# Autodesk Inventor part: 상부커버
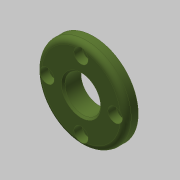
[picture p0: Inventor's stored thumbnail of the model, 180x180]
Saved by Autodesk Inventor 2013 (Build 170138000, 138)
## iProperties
Created: 2019-01
Part Number: 상부커버
Material: 알루미늄 6061
Document SubType Name: Modeling
Designer: mduedu
Density: 1 g/cm^3
Author: mduedu
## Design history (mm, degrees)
sketch "스케치1"
  geometry: L1 (0, 0)-(7, 0); L2 (7, 0)-(7, 25); L3 (7, 25)-(0, 25); L4 (0, 25)-(0, 0); L5 (7, 0)-(10, 0); L6 (10, 0)-(10, 14); L7 (10, 14)-(7, 14); L8 (7, 14)-(7, 0)
  constraints: 16 end point, 4 parallel, 2 horizontal, 2 perpendicular
  dimensions: "d0" = 50 diameter of L3 L1; "d2" = 10 distance between parallel lines of L6 L4; "d3" = 7 distance of L2.end L3.end; "d4" = 28 diameter of L7 L5
revolve "회전1" sketch "스케치1" stored, may be unused: angle "d5" = 90 deg
sketch "스케치2"
  geometry: C1 r 10 at (0, 0); 1 further point
  constraints: 1 centre point, 1 coincident
  dimensions: "d6" = 20 diameter of C1
extrude "돌출1" cut sketch "스케치2" stored distance "d7" = 10; taper "d8" = 0 deg
chamfer "모따기1" distance "d9" = 1; stored, may be unused: second distance "d10" = 2, angle "d11" = 45 deg
fillet "모깎기1" dims "d12" = 3
sketch "스케치3" dims "d13" = 38
  geometry: 6 further points
  constraints: 2 vertical alignment, 1 coincident, 7 other
  dimensions: "d16" = 360 deg dimension on point (0, 0) point (0, 19) (derived)
chamfer "모따기2" distance "d18" = 1; stored, may be unused: second distance "d19" = 2, angle "d20" = 45 deg
sketch "스케치4"
  geometry: 4 further points
  constraints: 4 other
hole "구멍1" sketch "스케치4" at (-19, 0), (0, -19), (19, 0), (0, 19) diameter "d21" = 4.5; stored, may be unused: countersink angle "d25" = 90 deg, drill point angle "d27" = 0 deg; dims "d22" = 6, "d23" = 8, "d24" = 4.6, "d26" = 8
node "솔리드1"
